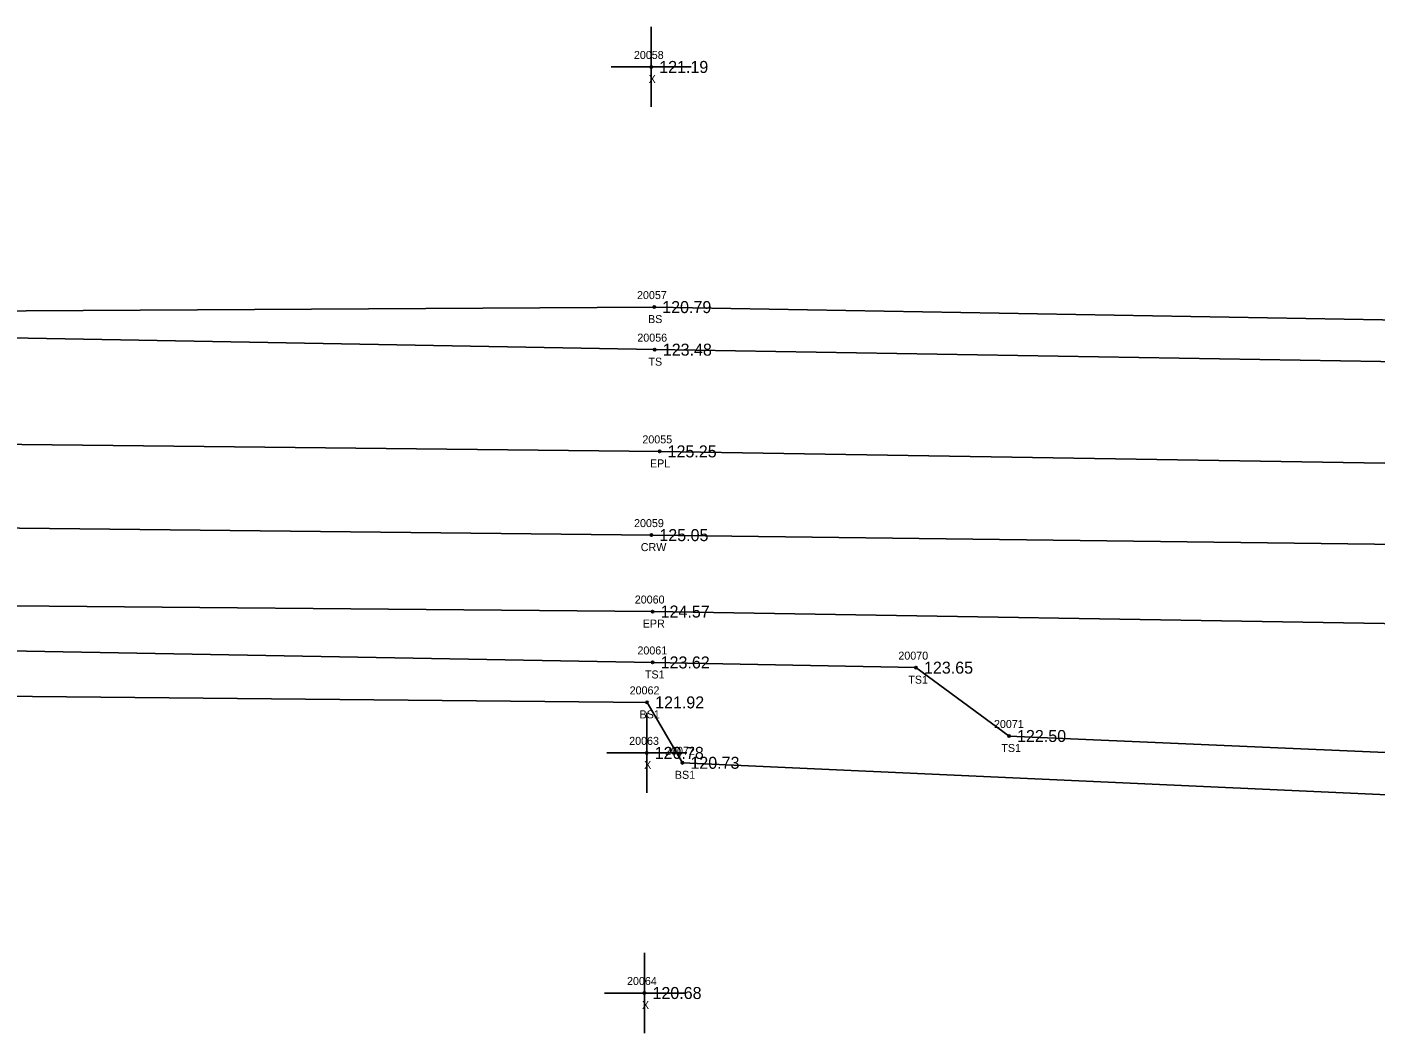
# Model space of a CAD drawing. Extents: x 2375812 to 2377225, y 1024470 to 1025135.
# Drawn here: x 2376046.3 to 2376214.8, y 1024870.2 to 1024995.9 of the extents above; entities that cross this region are included whole.
import ezdxf

# ---------------------------------------------------------------- set-up
doc = ezdxf.new("R2010")
doc.units = 0
for name, color, linetype in [('RD_DTM_BkLn1', 7, 'Continuous'), ('RD_DTM_BkLn2', 7, 'Continuous'), ('RD_DTM_BkLn_txCode', 7, 'Continuous'), ('RD_EX_Misc', 7, 'Continuous'), ('RD_EX_Misc_txCode', 7, 'Continuous'), ('RD_EX_Road', 7, 'Continuous'), ('RD_EX_Road_txCode', 7, 'Continuous'), ('RD_EX_TX_Misc_ELEV', 7, 'Continuous'), ('RD_EX_TX_Road_ELEV', 7, 'Continuous'), ('RD_HC_Survey_ELEV', 7, 'Continuous'), ('RD_HC_Survey_txCode', 7, 'Continuous'), ('RD_SMD_Locator', 7, 'Continuous')]:
    doc.layers.add(name, color=color, linetype=linetype)

msp = doc.modelspace()

# ---------------------------------------------------------------- linework, layer by layer
at = {"layer": 'RD_DTM_BkLn1'}
msp.add_lwpolyline([(2375816.52, 1024916.17), (2375868.08, 1024924.19), (2375918.61, 1024929.17), (2375973.79, 1024932.27), (2376030.31, 1024933.43), (2376124.39, 1024932.38), (2376221.5, 1024931.17), (2376315.07, 1024930.06), (2376410.07, 1024928.46), (2376471.65, 1024927.66)], dxfattribs=at)
at = {"layer": 'RD_DTM_BkLn2'}
for points in [[(2376029.54, 1024960.61), (2376031.93, 1024960.3), (2376124.75, 1024960.87), (2376220.58, 1024959.2), (2376313.51, 1024957.48), (2376410.53, 1024957.56), (2376415.87, 1024960.14)], [(2376030.33, 1024957.29), (2376124.82, 1024955.55), (2376220.6, 1024953.97), (2376313.35, 1024951.76), (2376409.92, 1024949.91), (2376424.84, 1024950.05)], [(2375828.21, 1024902.01), (2375869.58, 1024908.74), (2375919.97, 1024914.39), (2375974.42, 1024917.72), (2376030.13, 1024918.15), (2376124.55, 1024916.47), (2376157.47, 1024915.82), (2376169.1, 1024907.28), (2376220.97, 1024905.03), (2376312.67, 1024905.48), (2376408.92, 1024907.12), (2376437.56, 1024903.89), (2376467.32, 1024909.88), (2376471.6, 1024914.56)], [(2375828.74, 1024899.38), (2375869.85, 1024905.45), (2375920.89, 1024910.13), (2375974.62, 1024911.75), (2376029.89, 1024912.38), (2376123.86, 1024911.48), (2376128.27, 1024903.93), (2376220.97, 1024899.73), (2376312.35, 1024901.44), (2376410.93, 1024898.57), (2376439.29, 1024896.5), (2376469.35, 1024899.44), (2376491.09, 1024911.59)]]:
    msp.add_lwpolyline(points, dxfattribs=at)
at = {"layer": 'RD_EX_Misc'}
for p, q in [((2376124.37, 1024985.87), (2376124.37, 1024995.87)), ((2376119.37, 1024990.87), (2376129.37, 1024990.87)), ((2376123.81, 1024900.17), (2376123.81, 1024910.17)), ((2376118.81, 1024905.17), (2376128.81, 1024905.17)), ((2376123.53, 1024870.17), (2376123.53, 1024880.17)), ((2376118.53, 1024875.17), (2376128.53, 1024875.17))]:
    msp.add_line(p, q, dxfattribs=at)
at = {"layer": 'RD_EX_Road'}
for points in [[(2375814.75, 1024926.04), (2375866.75, 1024934.16), (2375917.59, 1024939.49), (2375973.63, 1024942.9), (2376030.48, 1024943.85), (2376125.42, 1024942.84), (2376221.25, 1024941.27), (2376314.97, 1024940.08), (2376410.64, 1024938.26), (2376471.87, 1024938.44)], [(2375818.02, 1024906.46), (2375868.67, 1024914.36), (2375919.37, 1024919.49), (2375974.01, 1024923.01), (2376030.21, 1024923.67), (2376124.55, 1024922.83), (2376221.09, 1024921.25), (2376314, 1024920.33), (2376408.92, 1024919.22), (2376471.42, 1024917.38)]]:
    msp.add_lwpolyline(points, dxfattribs=at)
at = {"layer": 'RD_SMD_Locator'}
for centre in [(2376124.37, 1024990.87), (2376124.75, 1024960.87), (2376124.82, 1024955.55), (2376125.42, 1024942.84), (2376124.39, 1024932.38), (2376124.55, 1024922.83), (2376124.55, 1024916.47), (2376157.47, 1024915.82), (2376123.86, 1024911.48), (2376169.1, 1024907.28), (2376123.81, 1024905.17), (2376128.27, 1024903.93), (2376123.53, 1024875.17)]:
    msp.add_circle(centre, 0.15, dxfattribs=at)

# ---------------------------------------------------------------- texts
at = {"layer": 'RD_DTM_BkLn_txCode'}
for s, p in [('20057', (2376122.6, 1024961.87)), ('BS', (2376123.98, 1024958.87)), ('20056', (2376122.64, 1024956.55)), ('TS', (2376124.03, 1024953.55)), ('20061', (2376122.65, 1024917.47)), ('20070', (2376155.27, 1024916.82)), ('TS1', (2376123.59, 1024914.47)), ('20062', (2376121.68, 1024912.48)), ('TS1', (2376156.51, 1024913.82)), ('BS1', (2376122.92, 1024909.48)), ('20071', (2376167.22, 1024908.28)), ('20072', (2376126.11, 1024904.93)), ('TS1', (2376168.14, 1024905.28)), ('BS1', (2376127.33, 1024901.93))]:
    msp.add_text(s, height=1, dxfattribs=at).set_placement(p)
at = {"layer": 'RD_EX_Misc_txCode'}
for s, p in [('20058', (2376122.21, 1024991.87)), ('X', (2376124.05, 1024988.87)), ('20063', (2376121.62, 1024906.17)), ('X', (2376123.49, 1024903.17)), ('20064', (2376121.35, 1024876.17)), ('X', (2376123.22, 1024873.17))]:
    msp.add_text(s, height=1, dxfattribs=at).set_placement(p)
at = {"layer": 'RD_EX_Road_txCode'}
for s, p in [('20055', (2376123.27, 1024943.84)), ('EPL', (2376124.22, 1024940.84)), ('20060', (2376122.32, 1024923.83)), ('EPR', (2376123.32, 1024920.83))]:
    msp.add_text(s, height=1, dxfattribs=at).set_placement(p)
at = {"layer": 'RD_EX_TX_Misc_ELEV'}
for s, p in [('121.19', (2376125.37, 1024990.12)), ('120.79', (2376125.75, 1024960.12)), ('123.48', (2376125.82, 1024954.8)), ('123.62', (2376125.55, 1024915.72)), ('123.65', (2376158.47, 1024915.07)), ('121.92', (2376124.86, 1024910.73)), ('122.50', (2376170.1, 1024906.53)), ('120.78', (2376124.81, 1024904.42)), ('120.73', (2376129.27, 1024903.18)), ('120.68', (2376124.53, 1024874.42))]:
    msp.add_text(s, height=1.5, dxfattribs=at).set_placement(p)
at = {"layer": 'RD_EX_TX_Road_ELEV'}
for s, p in [('125.25', (2376126.42, 1024942.09)), ('124.57', (2376125.55, 1024922.08))]:
    msp.add_text(s, height=1.5, dxfattribs=at).set_placement(p)
at = {"layer": 'RD_HC_Survey_ELEV'}
msp.add_text('125.05', height=1.5, dxfattribs=at).set_placement((2376125.39, 1024931.63))
at = {"layer": 'RD_HC_Survey_txCode'}
for s, p in [('20059', (2376122.23, 1024933.38)), ('CRW', (2376123.07, 1024930.38))]:
    msp.add_text(s, height=1, dxfattribs=at).set_placement(p)

doc.saveas('drawing.dxf')
